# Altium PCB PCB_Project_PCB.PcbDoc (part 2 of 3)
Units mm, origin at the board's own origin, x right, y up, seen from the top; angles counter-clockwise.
Board outline 185 x 95 mm, 2 copper layers (Top Layer, Bottom Layer), stack 1.575 mm thick; 173 components, 93 nets, 424 pads, 126 vias.
Unrouted connection lines stored in the file: 1.
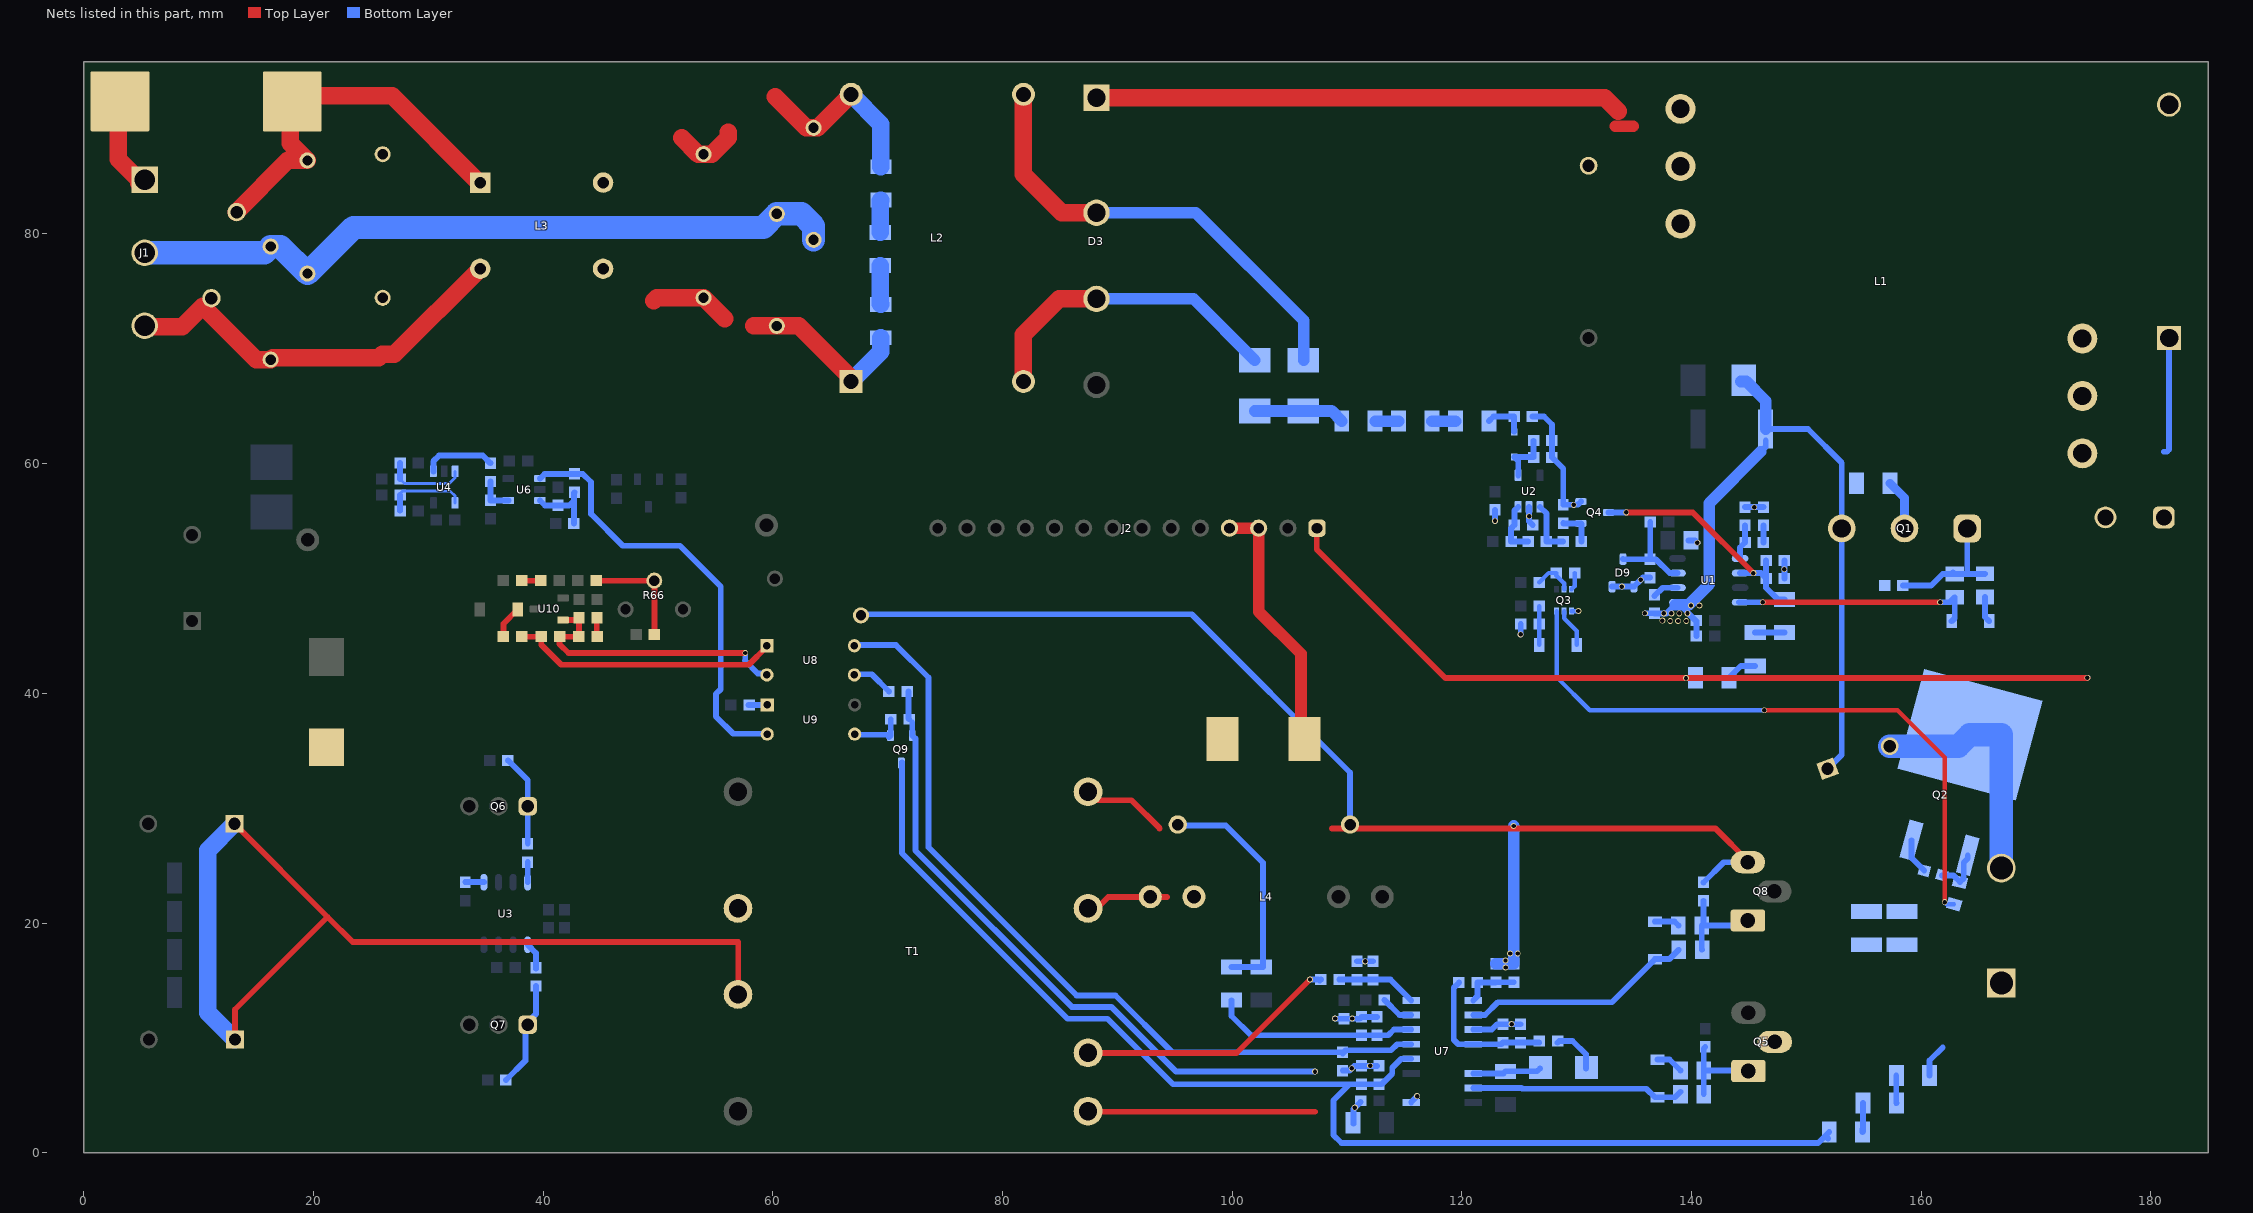
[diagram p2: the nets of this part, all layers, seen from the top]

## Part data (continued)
C48: "CAP, CERM, 0.12 µF, 25 V,+/- 10%, X7R, 0603", Cap_Case=0603, Manufacturer=MuRata, Supplier Part Number 1=GRM188R71E124KA01D-ND, TempCo=X7R, Tolerance_%=10, Value2=25V, ValueDisplayed=0.12µF
C50: "CAP, CERM, 0.33 µF, 16 V,+/- 10%, X7R, 0603", Cap_Case=0603, Manufacturer=MuRata, Supplier Part Number 1=490-3294-1-ND, TempCo=X7R, Tolerance_%=10, Value2=16V, ValueDisplayed=0.33µF
C51: "CAP, CERM, 1000 pF, 100 V,+/- 5%, X7R, 0603", Cap_Case=0603, Manufacturer=AVX, Supplier Part Number 1=478-3698-1-ND, TempCo=X7R, Tolerance_%=5, Value1="0.276 ohm", Value2=100V, ValueDisplayed=1000pF
C52: "CAP, CERM, 47 µF, 25 V,+/- 20%, JB, 1206", Cap_Case=1206, Manufacturer=TDK, Supplier Part Number 1=445-11717-1-ND, TempCo=JB, Tolerance_%=20, Value2=25V, ValueDisplayed=47µF
C54: library part CMP-0007347-5, "CAP, CERM, 4.7 uF, 25 V, +/- 10%, X5R, 0603", Cap_Case=0603, Manufacturer=MuRata, Supplier Part Number 1=490-7203-1-ND, TempCo=X5R, Tolerance_%=10%, Value1=Unknown, Value2=25V, ValueDisplayed=4.7uF
C55: "CAP, CERM, 10 pF, 50 V,+/- 5%, C0G/NP0, 0603", Cap_Case=0603, Manufacturer=MuRata, Supplier Part Number 1=490-1403-1-ND, TempCo=C0G/NP0, Tolerance_%=5, Value2=50V, ValueDisplayed=DNP
C57: library part CMP-0007377-4, "CAP, CERM, 0.01 uF, 16 V, +/- 10%, X7R, 0603", Cap_Case=0603, Manufacturer=MuRata, Supplier Part Number 1=490-1525-1-ND, TempCo=X7R, Tolerance_%=10%, Value1=Unknown, Value2=16V, ValueDisplayed=0.01uF
D1: "Diode, Switching-Bridge, 600 V, 3 A, TH", Manufacturer=Vishay-Semiconductor, Supplier Part Number 1=1N5406-E3/54GICT-ND, Value1=3A, Value2=1.2V
D2: "Diode, Ultrafast, 600 V, 8 A, TH", Manufacturer="ON Semiconductor", Supplier Part Number 1=MUR860GOS-ND, Value1=8A, Value2=0.98V
D3: library part GBJ2510-F, "Diode, Switching-Bridge, 600 V, 25 A, TH", Manufacturer=Vishay, Supplier Part Number 1=GBJ2510-FDI-ND, Value1=25A, Value2=1.05V
D4 D5 D15: "Diode, P-N, 1000 V, 1 A, SMB", Manufacturer="Diodes Inc.", Supplier Part Number 1=RS1MB-FDICT-ND, Value1=1A, Value2=1.3V
D6 D10 D11: library part CMP-0028358-1, "Diode, Schottky, 70 V, 0.015 A, SOD-123", Manufacturer="Diodes Inc.", PartNumber=1N5711W-7-F, Supplier Part Number 1=1N5711WDICT-ND, Value1=0.015A, Value2=1V
D7: "Diode, Schottky, 30V, 0.2A, SOD-323", Alternate PartNumber=BAT54, Manufacturer="ON Semiconductor", Supplier Part Number 1=BAT54HT1OSCT-ND, Value1=0.2A, Value2=0.35V
D8: "Diode, Zener, 5.6 V, 500 mW, SOD-123", Manufacturer="ON Semiconductor", Power_W=0.5, Supplier Part Number 1=MMSZ4690T1GOSCT-ND, Value1=0.5W
D9: "Diode, Switching, 250 V, 0.225 A, SOT-23", Manufacturer=Nexperia, Supplier Part Number 1=568-7986-1-ND, Value1=0.225A, Value2=1.25V
D12: library part MURS360T3G, "Diode, Ultrafast, 600 V, 3 A, SMC", Manufacturer=ST, Supplier Part Number 1=MURS360T3GOSCT-ND, Value1=3A, Value2=1.25V
D13: "Diode, Ultrafast, 600 V, 1 A, SMA", Manufacturer="Diodes Inc.", Supplier Part Number 1=US1J-FDICT-ND, Value1=1A, Value2=1.7V
D14: "Diode, Zener, 30 V, 500 mW, SOD-123", Manufacturer="Diodes Inc.", Power_W=0.5, Supplier Part Number 1=MMSZ5256B-FDICT-ND, Value1=0.5W
F1: library part 0678L9150-02, "Fuse, 10 A, 250 VAC", Irating_A=15, Manufacturer="Bel Fuse", Supplier Part Number 1=507-2062-1-ND
J1: "Header(Shrouded), 6.35mm, 3x1, Tin, TH", Color=Natural, Current_A=12, Manufacturer="TE Connectivity", Supplier Part Number 1=A1468-ND, Voltage_V=600
J2: "Header, 100 mil, 14x1, Tin, R/A, TH", Color=Natural, Manufacturer="TE Connectivity", Supplier Part Number 1=A30868-ND
L2: library part 7448258022, "Common Mode Filters / Chokes 5mH MIN", Manufacturer=Bourns, Supplier Part Number 1=542-8113-RC, Tolerance_%=30, ValueDisplayed="5 mH"
L3: library part 7448051804, "WE-CMBNC Common Mode Power Line Choke Nanocrystalline, Type XL, 4.5mH, 18A, 250V", DC Resistance max.=4.2mOhm, Insulation Test Voltage="1500V (AC)", Operating Temperature="-40 to +125degC", Rated Current=18A, Rated Voltage="250V (AC)"
L5: library part CMP-0062077-1, "Inductor, Ferrite, 300 nH, 32 A, 0.00031 ohm, SMD", Manufacturer="Pulse Engineering", Supplier Part Number 1=553-2161-1-ND, Value1="0.00031 ohm", Value2=32A, ValueDisplayed=300nH
Q1: "MOSFET, N-CH, 600 V, 31 A, TO-247", Alternate Manufacturer=None, Manufacturer="Infineon Technologies", Supplier Part Number 1=IPW60R099CP-ND, Value1="? ohm", Value2="60 nC"
Q2: library part AOB20S60L, "MOSFET, N-CH, 600 V, 20 A, DDPAK", Alternate Manufacturer=None, Manufacturer=AOS, Supplier Part Number 1=785-1247-1-ND, Value1="? ohm", Value2="19.8 nC"
Q3: library part "BC 846PN H6327, Infineon Technologies", "Transistor, NPN/PNP Pair, 65 V, 0.1 A, SOT-363", Manufacturer="Infineon Technologies", Supplier Part Number 1="BC 846PN H6327CT-ND", Value1="0.1 A", Value2=450
Q4 Q9: "MOSFET, N-CH, 60 V, 115 A, SOT-23", Alternate Manufacturer=None, Manufacturer="Fairchild Semiconductor", Supplier Part Number 1=2N7002NCT-ND, Value1="? ohm", Value2="? nC"
Q5 Q8: "MOSFET, N-CH, 650 V, 20.7 A, TO-220AB", Alternate Manufacturer=None, Manufacturer="Infineon Technologies", Supplier Part Number 1=SPP20N65C3XKSA1-ND, Value1="? ohm", Value2="87 nC"
Q6 Q7: library part CMP-0860023-1, "MOSFET, N-CH, 150 V, 100 A,", Alternate Manufacturer=None, Manufacturer="Infineon Technologies", Value1="? ohm", Value2="70 nC"
R1 R31 R41 R46 R50 R59: "RES, 10 k, 5%, 0.1 W, 0603", Manufacturer=Vishay-Dale, Power_W=0.1, Supplier Part Number 1=541-10KGCT-ND, TempCo="200 ppm/C", Tolerance_%=5, Value1=5%, Value2=0.1W, Value_Code=10k0, ValueDisplayed=10k
R2: "RES, 18.2, 1%, 0.125 W, 0805", Manufacturer=Vishay-Dale, Power_W=0.125, Supplier Part Number 1=541-18.2CCT-ND, TempCo="100 ppm/C", Tolerance_%=1, Value1=1%, Value2=0.125W, Value_Code=18R2, ValueDisplayed=18.2
R3: "RES, 0.02, 1%, 2 W, 2512", Manufacturer="Stackpole Electronics Inc", Power_W=2, Supplier Part Number 1=CSRN2512FK20L0CT-ND, TempCo="200 ppm/C", Tolerance_%=1, Value1=1%, Value2=2W, Value_Code=R020, ValueDisplayed=0.02
R4: library part CMP-0022705-3, "RES, 49.9 k, 1%, 0.1 W, AEC-Q200 Grade 0, 0603", Manufacturer=Panasonic, Power_W=100mW, Supplier Part Number 1=P49.9KHCT-ND, TempCo="100 ppm/C", Tolerance_%=1%, Value2=0.1W, Value_Code=49k9, ValueDisplayed=49.9k
R5: "RES, 3.3, 5%, 0.125 W, 0805", Manufacturer=Vishay-Dale, Power_W=0.125, Supplier Part Number 1=541-3.3ACT-ND, TempCo="200 ppm/C", Tolerance_%=5, Value1=5%, Value2=0.125W, Value_Code=3R30, ValueDisplayed=3.3
R6: "RES, 10, 5%, 0.125 W, 0805", Manufacturer=Vishay-Dale, Power_W=0.125, Supplier Part Number 1=541-10ACT-ND, TempCo="200 ppm/C", Tolerance_%=5, Value1=5%, Value2=0.125W, Value_Code=10R0, ValueDisplayed=10
R7 R9 R12: "RES, 3.0 M, 5%, 0.25 W, 1206", Manufacturer=Vishay-Dale, Power_W=0.25, Supplier Part Number 1=541-3.0MECT-ND, TempCo="200 ppm/C", Tolerance_%=5, Value1=5%, Value2=0.25W, Value_Code=3M00, ValueDisplayed=3.0M
R8 R16: "RES, 330 k, 5%, 0.25 W, 1206", Manufacturer=Vishay-Dale, Power_W=0.25, Supplier Part Number 1=541-330KECT-ND, TempCo="200 ppm/C", Tolerance_%=5, Value1=5%, Value2=0.25W, Value_Code=330k
R10: "RES, 10 k, 5%, 0.1 W, 0603", Manufacturer="Yageo America", Power_W=0.1, Supplier Part Number 1=311-10KGRCT-ND, TempCo="100 ppm/C", Tolerance_%=5, Value1=5%, Value2=0.1W, Value_Code=10k0, ValueDisplayed=10k
R11: "RES, 340 k, 1%, 0.25 W, 1206", Manufacturer=Vishay-Dale, Power_W=0.25, Supplier Part Number 1=541-340KFCT-ND, TempCo="100 ppm/C", Tolerance_%=1, Value1=1%, Value2=0.25W, Value_Code=340k
R13: "RES, 1.0 k, 5%, 0.1 W, 0603", Manufacturer=Vishay-Dale, Power_W=0.1, Supplier Part Number 1=541-1.0KGCT-ND, TempCo="200 ppm/C", Tolerance_%=5, Value1=5%, Value2=0.1W, Value_Code=1k00, ValueDisplayed=1.0k
R14: "RES, 220, 5%, 0.1 W, 0603", Manufacturer=Vishay-Dale, Power_W=0.1, Supplier Part Number 1=541-220GCT-ND, TempCo="200 ppm/C", Tolerance_%=5, Value1=5%, Value2=0.1W, Value_Code=220R, ValueDisplayed=220
R15 R18 R29 R40: "RES, 100 k, 5%, 0.1 W, 0603", Manufacturer=Vishay-Dale, Power_W=0.1, Supplier Part Number 1=541-100KGCT-ND, TempCo="200 ppm/C", Tolerance_%=5, Value1=5%, Value2=0.1W, Value_Code=100k
R17: "RES, 2.0 M, 5%, 0.1 W, 0603", Manufacturer=Vishay-Dale, Power_W=0.1, Supplier Part Number 1=541-2.0MGCT-ND, TempCo="200 ppm/C", Tolerance_%=5, Value1=5%, Value2=0.1W, Value_Code=2M00, ValueDisplayed=2.0M
R19: "RES, 12 k, 5%, 0.1 W, 0603", Manufacturer=Vishay-Dale, Power_W=0.1, Supplier Part Number 1=541-12KGCT-ND, TempCo="200 ppm/C", Tolerance_%=5, Value1=5%, Value2=0.1W, Value_Code=12k0, ValueDisplayed=12k
R20: "RES, 22 k, 5%, 0.1 W, 0603", Manufacturer=Vishay-Dale, Power_W=0.1, Supplier Part Number 1=541-22KGCT-ND, TempCo="200 ppm/C", Tolerance_%=5, Value1=5%, Value2=0.1W, Value_Code=22k0, ValueDisplayed=22k
R21: "RES, 13.0 k, 1%, 0.1 W, 0603", Manufacturer=Vishay-Dale, Power_W=0.1, Supplier Part Number 1=541-13.0KHCT-ND, TempCo="100 ppm/C", Tolerance_%=1, Value1=1%, Value2=0.1W, Value_Code=13k0, ValueDisplayed=13.0k
R22: "RES, 33 k, 5%, 0.125 W, 0805", Manufacturer=Vishay-Dale, Power_W=0.125, Supplier Part Number 1=541-33KACT-ND, TempCo="200 ppm/C", Tolerance_%=5, Value1=5%, Value2=0.125W, Value_Code=33k0, ValueDisplayed=33k
R23: "RES, 24 k, 5%, 0.1 W, 0603", Manufacturer="Yageo America", Power_W=0.1, Supplier Part Number 1=311-24KGRCT-ND, TempCo="100 ppm/C", Tolerance_%=5, Value1=5%, Value2=0.1W, Value_Code=24k0, ValueDisplayed=24k
R24 R64: "RES, 127 k, 1%, 0.1 W, 0603", Manufacturer=Vishay-Dale, Power_W=0.1, Supplier Part Number 1=541-127KHCT-ND, TempCo="100 ppm/C", Tolerance_%=1, Value1=1%, Value2=0.1W, Value_Code=127k
R25: "RES, 1.18 M, 1%, 0.1 W, 0603", Manufacturer=Vishay-Dale, Power_W=0.1, Supplier Part Number 1=541-1.18MHCT-ND, TempCo="100 ppm/C", Tolerance_%=1, Value1=1%, Value2=0.1W, Value_Code=1M18, ValueDisplayed=1.18M
R26 R65: "RES, 9.1 k, 5%, 0.1 W, 0603", Manufacturer=Vishay-Dale, Power_W=0.1, Supplier Part Number 1=541-9.1KGCT-ND, TempCo="200 ppm/C", Tolerance_%=5, Value1=5%, Value2=0.1W, Value_Code=9k10, ValueDisplayed=9.1k
R27 R35: library part CMP-0021945-2, "RES, 5.60, 1%, 0.125 W, 0805", Manufacturer="Yageo America", Power_W=125mW, Supplier Part Number 1=311-5.60CRCT-ND, TempCo="200 ppm/C", Tolerance_%=1%, Value2=0.125W, Value_Code=5R60, ValueDisplayed=5.60
R28 R42 R48: "RES, 2.0, 5%, 0.1 W, 0603", Manufacturer=Vishay-Dale, Power_W=0.1, Supplier Part Number 1=541-2.0GCT-ND, TempCo="200 ppm/C", Tolerance_%=5, Value1=5%, Value2=0.1W, Value_Code=2R00, ValueDisplayed=2.0
R30 R37: library part CMP-0021894-2, "RES, 1.00, 1%, 0.125 W, 0805", Manufacturer="Yageo America", Power_W=125mW, Supplier Part Number 1=311-1.00CRCT-ND, TempCo="200 ppm/C", Tolerance_%=1%, Value2=0.125W, Value_Code=1R00, ValueDisplayed=1.00
R32: "RES, 30, 5%, 0.1 W, 0603", Manufacturer=Vishay-Dale, Power_W=0.1, Supplier Part Number 1=541-30GCT-ND, TempCo="200 ppm/C", Tolerance_%=5, Value1=5%, Value2=0.1W, Value_Code=30R0, ValueDisplayed=30
R33: "RES, 33 k, 5%, 0.1 W, 0603", Manufacturer=Vishay-Dale, Power_W=0.1, Supplier Part Number 1=541-33KGCT-ND, TempCo="200 ppm/C", Tolerance_%=5, Value1=5%, Value2=0.1W, Value_Code=33k0, ValueDisplayed=33k
R34: "RES, 51 k, 5%, 0.1 W, 0603", Manufacturer=Vishay-Dale, Power_W=0.1, Supplier Part Number 1=541-51KGCT-ND, TempCo="200 ppm/C", Tolerance_%=5, Value1=5%, Value2=0.1W, Value_Code=51k0, ValueDisplayed=51k
R36: library part CMP-0015849-2, "RES, 0.0005, 1%, 2 W, 2512", Manufacturer=Vishay-Dale, Power_W=2W, TempCo="400 ppm/C", Tolerance_%=1%, Value_Code=L5000, ValueDisplayed=0.0005
R38: "RES, 8.2 k, 5%, 0.1 W, 0603", Manufacturer=Vishay-Dale, Power_W=0.1, Supplier Part Number 1=541-8.2KGCT-ND, TempCo="200 ppm/C", Tolerance_%=5, Value1=5%, Value2=0.1W, Value_Code=8k20, ValueDisplayed=8.2k
R39: "RES, 68, 5%, 0.1 W, 0603", Manufacturer=Vishay-Dale, Power_W=0.1, Supplier Part Number 1=541-68GCT-ND, TempCo="200 ppm/C", Tolerance_%=5, Value1=5%, Value2=0.1W, Value_Code=68R0, ValueDisplayed=68
R43 R44: library part CMP-0022004-4, "RES, 10.0, 1%, 0.25 W, AEC-Q200 Grade 0, 0603", Manufacturer=Vishay-Dale, Power_W=250mW, Supplier Part Number 1=541-10.0SCT-ND, TempCo="100 ppm/C", Tolerance_%=1%, Value2=0.25W, Value_Code=10R0, ValueDisplayed=10.0
R45: "RES, 1.0 k, 5%, 0.1 W, 0603", Manufacturer="Yageo America", Power_W=0.1, Supplier Part Number 1=311-1.0KGRCT-ND, TempCo="100 ppm/C", Tolerance_%=5, Value1=5%, Value2=0.1W, Value_Code=1k00, ValueDisplayed=1.0k
R47: "RES, 24.3 k, 1%, 0.1 W, 0603", Manufacturer=Vishay-Dale, Power_W=0.1, Supplier Part Number 1=541-24.3KHCT-ND, TempCo="100 ppm/C", Tolerance_%=1, Value1=1%, Value2=0.1W, Value_Code=24k3, ValueDisplayed=24.3k
R49: "RES, 110 k, 5%, 0.1 W, 0603", Manufacturer=Vishay-Dale, Power_W=0.1, Supplier Part Number 1=541-110KGCT-ND, TempCo="200 ppm/C", Tolerance_%=5, Value1=5%, Value2=0.1W, Value_Code=110k
R51 R53: "RES, 5.1 M, 5%, 0.25 W, 1206", Manufacturer=Vishay-Dale, Power_W=0.25, Supplier Part Number 1=541-5.1MECT-ND, TempCo="200 ppm/C", Tolerance_%=5, Value1=5%, Value2=0.25W, Value_Code=5M10, ValueDisplayed=5.1M
R52: "RES, 75 k, 5%, 0.1 W, 0603", Manufacturer=Vishay-Dale, Power_W=0.1, Supplier Part Number 1=541-75KGCT-ND, TempCo="200 ppm/C", Tolerance_%=5, Value1=5%, Value2=0.1W, Value_Code=75k0, ValueDisplayed=75k
R54: "RES, 470 k, 5%, 0.1 W, 0603", Manufacturer=Vishay-Dale, Power_W=0.1, Supplier Part Number 1=541-470KGCT-ND, TempCo="200 ppm/C", Tolerance_%=5, Value1=5%, Value2=0.1W, Value_Code=470k
R55: "RES, 6.04 k, 1%, 0.1 W, 0603", Manufacturer=Vishay-Dale, Power_W=0.1, Supplier Part Number 1=541-6.04KHCT-ND, TempCo="100 ppm/C", Tolerance_%=1, Value1=1%, Value2=0.1W, Value_Code=6k04, ValueDisplayed=6.04k
R56: "RES, 130 k, 5%, 0.1 W, 0603", Manufacturer=Vishay-Dale, Power_W=0.1, Supplier Part Number 1=541-130KGCT-ND, TempCo="200 ppm/C", Tolerance_%=5, Value1=5%, Value2=0.1W, Value_Code=130k
R57 R63: "RES, 10 k, 5%, 0.1 W, 0603", Manufacturer="Samsung Electro-Mechanics", Power_W=0.1, Supplier Part Number 1=1276-5086-1-ND, TempCo="100 ppm/C", Tolerance_%=5, Value1=5%, Value2=0.1W, Value_Code=10k0, ValueDisplayed=10k
R58: "RES, 0, 1%, 0.1 W, AEC-Q200 Grade 0, 0603", Manufacturer="Stackpole Electronics Inc", Power_W=0.1, Supplier Part Number 1=RMCF0603ZT0R00CT-ND, TempCo=ppm/C, Tolerance_%=1, Value1=1%, Value2=0.1W, Value_Code=0
R60: "RES, 5.6 M, 5%, 0.25 W, 1206", Manufacturer=Vishay-Dale, Power_W=0.25, Supplier Part Number 1=541-5.6MECT-ND, TempCo="200 ppm/C", Tolerance_%=5, Value1=5%, Value2=0.25W, Value_Code=5M60, ValueDisplayed=5.6M
R61: "RES, 330 k, 5%, 0.1 W, 0603", Manufacturer=Vishay-Dale, Power_W=0.1, Supplier Part Number 1=541-330KGCT-ND, TempCo="200 ppm/C", Tolerance_%=5, Value1=5%, Value2=0.1W, Value_Code=330k
R62: "RES, 0, 5%, 0.1 W, 0603", Manufacturer=Vishay-Dale, Power_W=0.1, Supplier Part Number 1=541-0.0GCT-ND, TempCo="200 ppm/C", Tolerance_%=5, Value1=5%, Value2=0.1W, Value_Code=0000, ValueDisplayed=0
R66: library part CMP-0001795-2, "Trimmer Potentiometer, Lead Sealed Type Multiturn PV37 Series, TH", Manufacturer=Bourns, Supplier Part Number 1=490-2983-ND
R67 R68 R69: library part CMP-0018205-2, "RES, 330 k, 1%, 0.25 W, 1206", Manufacturer="Yageo America", Power_W=250mW, Supplier Part Number 1=311-330KFRCT-ND, TempCo="100 ppm/C", Tolerance_%=1%, Value2=0.25W, Value_Code=330k
RF1: "RES, 47, 10%, 2 W, Axial resistor", Manufacturer="TT Electronics/IRC", Power_W=2, Supplier Part Number 1=985-1022-1-ND, TempCo="100 ppm/C", Tolerance_%=10, Value1=10%, Value2=2W, Value_Code=47R0, ValueDisplayed=47
RV1: "Varistor 275V RMS 10MM Radial, TH", Manufacturer=TDK, Supplier Part Number 1=495-1433-ND
T1: library part 760895431, "WE-LLCR Resonant Converter, size PQ3232, 155uH, 16:4:4:1 , 500W", Inductance=600uH, Input Voltage="360-400 V DC", Output Power=500W
U1: library part CMP-0074100-1, "8-PIN CONTINUOUS CONDUCTION MODE (CCM) PFC CONTROLLER, D0008A (SOIC-8)", Alternate Manufacturer="Texas Instruments", Alternate PartNumber=UCC28180D
U2: library part CMP-0073526-1, "36V, Low-Power, RRO, General-Purpose Operational Amplifier, DBV0005A (SOT-23-5)", Alternate Manufacturer="Texas Instruments", Alternate PartNumber=TLV171IDBVT
U3: library part CMP-0079610-1, "High Performance Synchronous Rectifier Driver for LLC Resonant Converter, D0008A (SOIC-8)", Alternate Manufacturer="Texas Instruments"
U4: library part CMP-0013052-2, "Low- and High-Side Measurement, Multichannel, Voltage Output, Current-Sense Amplifier, DBV0005A (SOT-5)", Alternate Manufacturer="Texas Instruments"
U5: library part CMP-0074893-1, "100-mA, 30-V, Fixed-Output, Linear-Voltage Regulator, DBZ0003A (SOT-23-3)", Alternate Manufacturer="Texas Instruments", Alternate PartNumber=TLV76033DBZT
U6: library part CMP-0081550-1, "Low-Power, Rail-to-Rail In and Out, 1-MHz Operational Amplifier, DBV0005A (SOT-23-5)", Alternate Manufacturer="Texas Instruments", Alternate PartNumber=TLV9001IDBVT
U7: library part CMP-0077204-4, "LLC Resonant Controller Enabling Low Standby Power, DDB0014A (SOIC-14)", Alternate Manufacturer="Texas Instruments", Alternate PartNumber=UCC25630-3DDBT, Operating Temperature Range="-40 to 125 C", PartNumber=UCC25640-3DDBR, Rating=Catalog
U8 U9: "Optocoupler, 5.3 kV, 50-600% CTR, TH", Manufacturer=Vishay-Semiconductor, Supplier Part Number 1=VO618A-ND, Voltage_Isolation_Vrms=5300V
U10: library part CMP-0066200-1, "2.5V Low Iq Adjustable Precision Shunt Regulator, DBZ0003A (SOT-23-3)", Alternate Manufacturer="Texas Instruments", Alternate PartNumber=ATL431BQDBZT
ZZ1: library part CMP-0003616-3
ZZ2: library part CMP-0077236-1
ZZ3: library part CMP-0077237-1
ZZ4: library part CMP-0077238-1

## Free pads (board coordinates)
  round 2 hole 1.2: 2(59.461,54.635) 3(19.507,53.365)

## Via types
v1: diameter 0.508, hole 0.381, Top Layer to Bottom Layer, 124 vias
v2: diameter 2.54, hole 2.032, Top Layer to Bottom Layer, 2 vias

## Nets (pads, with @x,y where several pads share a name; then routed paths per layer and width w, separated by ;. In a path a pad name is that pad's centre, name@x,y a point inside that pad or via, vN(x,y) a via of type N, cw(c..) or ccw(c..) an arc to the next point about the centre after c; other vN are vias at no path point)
12V: C49.1 C54.2 R48.1 R54.2 U7.12 | length 12.8
  Bottom Layer w0.508: R54.2@119.753,14.808 119.304,14.359 119.304,9.83 119.685,9.449 U7.12@120.992,9.449 123.435,9.449 C54.2@123.575,9.589 C49.1@125.099,9.589 126.725,9.589 R48.1@126.738,9.576
390V: C1.1 C6.1 C7.1 D1.1 D2.1 J2.1 Q5.2 R8.2 R51.2 | length 87.6
  Top Layer w0.508: J2.1@107.366,54.381 107.366,52.527 118.567,41.326 v1(139.522,41.326) 174.447,41.326 v1(174.473,41.351)
  Bottom Layer w0.508: v1(139.522,41.326) 139.548,41.351 R8.2@140.358,41.351 ; R51.2@160.733,6.731 160.733,8.029 161.874,9.169 ; 181.127,61.036 181.381,61.036 181.585,61.239 D1.1@181.585,70.942
ACSNS: C14.1 D7.1 R17.2 U2.4 | length 4.9
  Bottom Layer w0.508: U2.4@124.907,58.982 124.907,60.226 D7.1@124.562,60.571 126.233,60.571 C14.1@126.251,60.554 R17.2@126.251,62.001
BLK: C57.1 Q9.3 R60.1 R64.2 U7.4 | length 111
  Bottom Layer w0.508: Q9.3@71.247,34.004 71.247,26.086 85.674,11.659 89.154,11.659 94.856,5.956 110.223,5.956 ; U7.4@115.592,8.179 114.732,8.179 113.944,7.391 113.944,6.883 113.017,5.956 C57.1@112.776,5.956 R64.2@111.256,5.956 110.223,5.956 ; R60.1@151.892,1.245 R60.1@151.663,1.473 ; R60.1@151.994,1.803 R60.1@151.663,1.473 ; 110.223,5.956 108.814,4.547 108.814,1.549 109.525,0.838 151.028,0.838 R60.1@151.663,1.473
BW: C56.1 R33.1 R38.2 U7.8 | length 7
  Bottom Layer w0.508: R33.1@109.334,15.088 109.347,15.075 C56.1@110.875,15.075 R38.2@112.272,15.075 113.776,15.075 U7.8@115.592,13.259
DRV: Q3.3 R2.2 | length 55.9
  Top Layer w0.381: v1(146.329,38.532) 157.937,38.532 162.052,34.417 v1(162.052,21.819)
  Bottom Layer w0.381: Q3.3@128.255,47.163 128.255,41.417 131.14,38.532 v1(146.329,38.532) ; v1(162.052,21.819) 162.231,21.64 R2.2@162.86,21.64
EARTH: C2.2 C3.1 C11.1 C12.1 J1.2 | length 63.5
  Bottom Layer w1.016: J1.2@5.08,78.359 J1.2@5.309,78.359
  Bottom Layer w2.032: J1.2@5.309,78.359 15.739,78.359 C3.1@16.282,78.902 17.136,78.902 C12.1@19.482,76.556 23.487,80.561 59.165,80.561 C2.2@60.351,81.746 62.5,81.746 63.551,80.696 C11.1@63.551,79.493
FB: C51.1 U7.5 U8.4 | length 72.2
  Bottom Layer w0.508: U8.4@67.107,44.196 70.739,44.196 73.558,41.377 73.558,26.594 86.462,13.691 89.84,13.691 94.78,8.75 C51.1@109.626,8.75 ; C51.1@109.626,8.649 109.893,8.915 113.843,8.915 114.376,9.449 U7.5@115.592,9.449
G1: R42.1 U3.1 | length 2.4
  Bottom Layer w0.508: U3.1@38.659,18.103 39.37,17.392 R42.1@39.37,16.015
G2: R28.2 U3.8 | length 1.8
  Bottom Layer w0.508: U3.8@38.659,23.553 R28.2@38.659,25.311
HO: D10.1 R27.1 U7.15 | length 18.6
  Bottom Layer w0.508: U7.15@120.992,5.639 125.197,5.639 125.261,5.574 136.069,5.574 136.818,4.826 138.557,4.826 R27.1@139.04,5.309
I_OUT: R45.1 U4.1 | length 6.3
  Bottom Layer w0.508: U4.1@30.444,59.325 30.444,60.2 30.95,60.706 34.747,60.706 R45.1@35.408,60.045
ISNS: C26.2 C38.1 R39.2 U7.6 | length 17.9
  Bottom Layer w0.508: C26.2@99.949,13.282 99.949,11.913 101.638,10.224 R39.2@111.256,10.224 C38.1@112.628,10.224 113.602,10.224 114.097,10.719 U7.6@115.592,10.719
LATCH: R49.1 U6.1 U9.2 | length 38.2
  Bottom Layer w0.508: U6.1@39.729,58.697 40.138,59.106 R49.1@42.748,59.106 43.46,59.106 44.171,58.395 44.171,55.626 46.939,52.857 51.918,52.857 55.474,49.301 55.474,40.361 55.067,39.954 55.067,37.973 56.566,36.474 U9.2@59.512,36.474
LL/SS: C50.1 R54.1 R61.2 U7.9 | length 4.9
  Bottom Layer w0.508: U7.9@120.992,13.259 121.353,13.619 R54.1@121.353,14.808 122.927,14.808 R61.2@122.966,14.846 C50.1@124.515,14.846
LO: D11.1 R35.1 U7.10 | length 20.3
  Bottom Layer w0.508: U7.10@120.992,11.989 122.022,11.989 123.139,13.106 133.071,13.106 D11.1@136.818,16.854 ; D11.1@136.804,16.854 D11.1@136.818,16.854 ; R35.1@138.887,17.678 138.063,16.854 D11.1@136.818,16.854
NetA: D4.1 D5.1 R7.2 | length 7.9
  Bottom Layer w1.016: D5.1@101.981,64.592 D4.1@106.197,64.592 108.659,64.592 R7.2@109.548,63.703
NetC1_2: C1.2 Q2.4 RF1.2 | length 21.8
  Bottom Layer w2.032: RF1.2@157.259,35.396 163.235,35.396 Q2.4@164.243,36.404 166.98,36.404 C1.2@166.98,24.787
NetC2_1: C2.1 C10.1 L2.6 L3.4 R67.2 | length 22
  Top Layer w1.524: 52.07,88.367 53.491,86.946 C10.1@53.975,86.946 54.688,86.946 56.134,88.392 56.134,88.875 ; 60.228,91.944 62.925,89.246 C2.1@63.551,89.246 63.916,89.246 L2.6@66.827,92.158
  Bottom Layer w1.524: L2.6@66.827,92.158 69.418,89.567 R67.2@69.418,85.854
NetC3_2: C3.2 C4.1 F1.1 L3.1 RV1.2 | length 33.7
  Top Layer w1.524: RV1.2@13.267,81.906 17.762,86.402 C3.2@19.482,86.402 17.997,87.886 17.997,91.542 18.478,92.022 25.984,92.022 26.85,92.022 L3.1@34.464,84.408
NetC4_2: C4.2 C12.2 J1.3 L3.2 RV1.1 | length 35.4
  Top Layer w1.524: J1.3@5.08,71.933 8.594,71.933 10.367,73.707 15.018,69.056 C12.2@16.282,69.056 16.467,69.24 25.703,69.24 25.984,69.522 27.053,69.522 L3.2@34.515,76.984
NetC5_1: C5.1 D1.2 D3.1 L1.1 | length 47.5
  Top Layer w1: 133.368,89.383 134.925,89.383
  Top Layer w1.524: D3.1@88.189,91.853 132.427,91.853 133.604,90.676
NetC10_2: C10.2 C11.2 L2.1 L3.3 R69.1 | length 22.6
  Top Layer w1.524: 49.632,74.193 49.884,74.446 C10.2@53.975,74.446 53.977,74.446 55.804,72.619 ; 58.353,71.993 C11.2@60.351,71.993 62.272,71.993 66.827,67.437 L2.1@66.827,67.158
  Bottom Layer w1.524: L2.1@66.827,67.158 69.407,69.738 R69.1@69.407,70.965
NetC13_1: C13.1 D2.3 L1.2 Q1.2 | length 4.5
  Bottom Layer w0.762: C13.1@157.279,58.293 158.547,57.025 Q1.2@158.547,54.356
NetC15_1: C15.1 D8.1 R13.1 | length 3.4
  Bottom Layer w0.381: D8.1@126.734,44.221 C15.1@126.733,46.05 R13.1@126.733,47.6
NetC16_1: C16.1 D9.3 R14.1 U1.3 | length 8.5
  Bottom Layer w0.508: D9.3@134.036,51.695 134.055,51.676 C16.1@136.398,51.676 ; R14.1@136.411,54.915 136.411,51.689 C16.1@136.398,51.676 ; U1.3@138.778,50.469 138.1,50.469 136.893,51.676 C16.1@136.398,51.676
NetC18_1: C18.1 U1.2 | length 2.3
  Bottom Layer w0.508: C18.1@136.779,48.49 137.488,49.199 U1.2@138.778,49.199
NetC19_1: C19.1 Q4.3 R16.1 R21.2 U1.6 | length 21.7
  Top Layer w0.508: v1(134.315,55.753) 140.106,55.753 v1(145.39,50.469)
  Bottom Layer w0.508: Q4.3@132.772,55.753 v1(134.315,55.753) ; U1.6@144.228,50.469 v1(145.39,50.469) 146.038,50.469 R21.2@146.495,50.013 ; C19.1@146.495,51.562 R21.2@146.495,50.013 ; 146.507,49.2 146.495,49.212 ; R16.1@148.107,48.186 147.509,48.186 146.495,49.2 146.495,49.212 ; 146.495,49.212 R21.2@146.495,50.013
NetC20_1: C20.1 R20.2 U1.5 | length 3.1
  Bottom Layer w0.508: U1.5@144.228,51.739 144.228,52.699 R20.2@144.666,53.137 144.653,53.15 C20.1@144.653,54.622
NetC21_1: C21.1 R20.1 | length 1.5
  Bottom Layer w0.508: R20.1@146.266,53.137 146.279,53.15 C21.1@146.279,54.622
NetC25_1: C25.1 C26.1 C31.1 D12.1 T1.3 | length 27.9
  Top Layer w0.508: T1.3@87.478,30.694 91.237,30.694 93.687,28.245
  Bottom Layer w0.508: C31.1@95.268,28.245 95.522,28.499 99.441,28.499 102.692,25.248 102.692,16.182 C25.1@102.54,16.182 C26.1@99.949,16.182
NetC27_1: C27.1 C28.1 C32.1 C33.1 C34.1 C35.1 L5.1 T1.9 T1.10 | length 88.2
  Top Layer w0.508: C27.1@13.123,28.642 21.23,20.534 ; C28.1@13.173,9.855 13.173,12.478 21.23,20.534 ; T1.9@56.998,13.044 56.998,18.339 23.426,18.339 21.23,20.534
  Bottom Layer w1.524: C27.1@13.123,28.642 10.823,26.342 C34.1@10.823,23.901 C32.1@10.823,17.247 C35.1@10.823,13.945 10.823,12.206 C28.1@13.173,9.855
NetC44_1: C44.1 R43.1 U4.3 | length 7.1
  Bottom Layer w0.254: R43.1@27.546,58.661 27.927,58.28 31.826,58.28 32.344,58.798 U4.3@32.344,59.325
  Bottom Layer w0.508: R43.1@27.546,58.661 C44.1@27.546,60.058
NetC45_1: C45.1 R44.1 U4.4 | length 7.1
  Bottom Layer w0.254: R44.1@27.546,57.391 27.775,57.62 31.902,57.62 32.344,57.178 U4.4@32.344,56.575
  Bottom Layer w0.508: C45.1@27.546,55.893 R44.1@27.546,57.264
NetC46_1: C46.1 R45.2 U6.4 | length 3.2
  Bottom Layer w0.508: R45.2@35.408,58.445 C46.1@35.408,56.794 36.976,56.794 U6.4@36.979,56.797
NetC47_1: C47.1 D13.1 U7.14 | length 6
  Bottom Layer w0.508: U7.14@120.992,6.909 123.624,6.909 C47.1@123.804,7.089 126.552,7.089 D13.1@126.803,7.341
NetC48_1: C48.1 R59.2 | length 1.7
  Top Layer w0.508: R59.2@44.679,46.571 44.679,44.971 C48.1@44.717,44.933
NetC48_2: C48.2 C55.2 R55.1 U8.2 U10.1 | length 24.9
  Top Layer w0.508: U10.1@41.738,46.396 42.954,46.396 C55.2@43.117,46.558 ; C55.2@43.129,46.571 C55.2@43.117,46.558 ; v1(57.607,43.51) 42.215,43.51 41.44,44.285 R55.1@41.44,44.933 C48.2@43.117,44.933 C55.2@43.117,46.558
  Bottom Layer w0.508: v1(57.607,43.51) 57.607,42.875 57.582,42.85 58.699,41.732 U8.2@59.461,41.732
NetD3_2: D3.2 D4.2 L2.7 | length 40.1
  Top Layer w1.524: L2.7@81.827,92.158 81.827,85.183 85.157,81.853 D3.2@88.189,81.853
  Bottom Layer w1.016: D3.2@88.189,81.853 96.836,81.853 106.223,72.466 D4.2@106.223,69.012
NetD3_3: D3.3 D5.2 L2.12 | length 27.7
  Top Layer w1.524: L2.12@81.827,67.158 81.827,71.236 84.945,74.353 D3.3@88.189,74.353
  Bottom Layer w1.016: D3.3@88.189,74.353 96.64,74.353 D5.2@101.981,69.012
NetD6_1: D6.1 R6.1 U1.8 | length 21.3
  Top Layer w0.508: v1(146.202,47.93) v1(161.646,47.929)
  Bottom Layer w0.508: U1.8@144.228,47.929 144.127,47.929 v1(146.202,47.93) ; v1(161.646,47.929) 162.483,47.929 R6.1@162.916,48.362 162.916,46.545 D6.1@162.65,46.279
NetD6_2: D6.2 R5.1 | length 2.3
  Bottom Layer w0.508: R5.1@165.557,48.387 165.557,46.646 D6.2@165.925,46.279
NetD7_2: D7.2 R12.1 R18.2 | length 3.7
  Bottom Layer w0.508: R12.1@122.354,63.703 122.76,64.11 R18.2@124.549,64.11 124.549,62.784 D7.2@124.562,62.771
NetD8_2: D8.2 Q3.2 | length 3.4
  Bottom Layer w0.381: Q3.2@128.905,47.163 128.905,46.532 130.009,45.429 D8.2@130.009,44.221
NetD10_2: D10.2 R30.1 | length 2.4
  Bottom Layer w0.508: D10.2@137.033,8.114 138.088,8.114 R30.1@139.04,7.163
NetD11_2: D11.2 R37.1 | length 2.2
  Bottom Layer w0.508: D11.2@136.804,20.129 138.52,20.129 R37.1@138.862,19.787
NetD13_2: D13.2 R48.2 | length 4.2
  Bottom Layer w0.508: R48.2@128.338,9.576 128.49,9.728 129.642,9.728 130.803,8.566 D13.2@130.803,7.341
NetD14_2: D14.2 R50.2 | length 2.9
  Top Layer w0.508: R50.2@36.551,44.933 36.551,46.064 D14.2@37.782,47.295
NetF1_2: F1.2 J1.1 | length 7.9
  Top Layer w1.524: F1.2@2.997,91.542 2.997,86.512 4.775,84.734 J1.1@4.775,84.404
NetL4_2: L4.2 T1.1 | length 7.6
  Top Layer w0.508: T1.1@87.478,20.534 89.209,22.266 94.335,22.266
NetQ1_1: Q1.1 R1.2 R5.2 R6.2 | length 10.7
  Bottom Layer w0.508: R1.2@158.407,49.378 160.858,49.378 161.874,50.394 R6.2@162.916,50.394 ; R6.2@162.763,50.546 R6.2@162.916,50.394 ; Q1.1@164.008,53.264 164.008,50.47 163.932,50.394 ; R5.2@165.557,50.419 165.532,50.394 163.932,50.394 ; R6.2@162.916,50.394 163.932,50.394
NetQ2_1: Q2.1 R2.1 R4.1 | length 4.4
  Bottom Layer w0.508: R4.1@161.809,24.152 162.798,24.152 R2.1@163.378,23.572 163.703,23.897 163.703,25.273 164.056,25.626 Q2.1@164.056,25.894
NetQ3_5: Q3.5 R10.1 R15.2 | length 3.5
  Bottom Layer w0.381: R10.1@126.746,49.662 127.559,50.475 R15.2@128.22,50.475 128.22,50.266 128.905,49.58 Q3.5@128.905,49.063
NetQ3_6: Q3.6 R15.1 | length 1.5
  Bottom Layer w0.381: Q3.6@129.555,49.063 129.82,49.327 R15.1@129.82,50.475
NetQ4_1: Q4.1 R19.1 R23.2 | length 3.2
  Bottom Layer w0.508: R23.2@128.829,54.826 128.852,54.803 Q4.1@130.372,54.803 130.416,54.759 R19.1@130.416,53.213
NetQ5_1: Q5.1 R27.2 R30.2 R31.2 | length 8.1
  Bottom Layer w0.508: R27.2@141.072,5.105 R30.2@141.072,7.163 ; R31.2@141.199,9.208 141.072,9.081 R30.2@141.072,7.163 ; Q5.1@144.958,7.112 144.907,7.163 R30.2@141.072,7.163
NetQ6_1: Q6.1 R28.1 R29.1 | length 8
  Bottom Layer w0.508: R29.1@36.944,34.163 38.659,32.448 Q6.1@38.659,30.175 R28.1@38.659,26.911
NetQ7_1: Q7.1 R40.1 R42.2 | length 9.3
  Bottom Layer w0.508: R40.1@36.766,6.325 38.456,8.014 38.456,11.151 39.37,12.065 R42.2@39.37,14.516
NetQ8_1: Q8.1 R35.2 R37.2 R41.2 | length 8.5
  Bottom Layer w0.508: R35.2@140.919,17.678 140.894,17.704 R37.2@140.894,19.787 ; R41.2@141.046,21.933 141.046,19.939 R37.2@140.894,19.787 ; Q8.1@144.907,20.218 144.475,19.787 R37.2@140.894,19.787
NetQ9_1: Q9.1 R63.1 U9.3 | length 4.5
  Bottom Layer w0.508: U9.3@67.158,36.398 Q9.1@70.015,36.398 ; Q9.1@70.119,36.176 70.269,36.326 R63.1@70.269,37.744
NetR7_1: R7.1 R9.2 | length 2.1
  Bottom Layer w1.016: R7.1@112.448,63.703 R9.2@114.501,63.703
NetR8_1: R8.1 R11.2 | length 2.7
  Bottom Layer w0.508: R8.1@143.258,41.351 144.302,42.395 145.538,42.395 R11.2@145.542,42.39
NetR9_1: R9.1 R12.2 | length 2.1
  Bottom Layer w1.016: R9.1@117.401,63.703 R12.2@119.454,63.703
NetR11_1: R11.1 R16.2 | length 2.6
  Bottom Layer w0.508: R11.1@145.542,45.29 148.103,45.29 R16.2@148.107,45.286
NetR24_1: R24.1 R25.1 R26.2 U2.3 | length 4.7
  Bottom Layer w0.508: U2.3@124.907,56.232 124.574,55.9 R26.2@124.574,54.661 124.295,54.381 R24.1@124.295,53.213 125.763,53.213 R25.1@125.768,53.208
NetR32_2: R32.2 U3.5 | length 1.6
  Bottom Layer w0.508: R32.2@33.223,23.558 34.843,23.558 U3.5@34.849,23.553
NetR33_2: R33.2 T1.5 | length 23.3
  Top Layer w0.508: T1.5@87.478,7.964 88.2,8.687 100.381,8.687 v1(106.782,15.088)
  Bottom Layer w0.508: v1(106.782,15.088) 107.531,15.088 107.633,14.986 R33.2@107.734,15.088
NetR34_2: R34.2 R65.1 R66.2 | length 9.7
  Top Layer w0.508: R65.1@44.64,49.809 R66.2@49.682,49.809 49.695,49.797 R34.2@49.695,45.136
NetR46_2: R46.2 R47.2 R49.2 U6.3 | length 6.1
  Bottom Layer w0.508: U6.3@39.729,56.797 40.163,56.363 R47.2@41.3,56.363 42.253,56.363 42.685,56.794 ; R46.2@42.685,54.788 42.685,56.794 ; R49.2@42.748,57.506 42.685,57.442 42.685,56.794
NetR50_1: R50.1 R55.2 U8.1 | length 23.6
  Top Layer w0.508: R50.1@38.151,44.933 R55.2@39.84,44.933 39.84,44.234 41.58,42.494 57.912,42.494 59.461,44.044 U8.1@59.461,44.272
NetR51_1: R51.1 R53.2 | length 2.4
  Bottom Layer w0.508: R51.1@157.833,6.731 157.833,4.322 R53.2@157.838,4.318
NetR52_1: R52.1 R56.2 | length 1.7
  Top Layer w0.508: R52.1@38.138,49.809 R56.2@39.789,49.809
NetR53_1: R53.1 R60.2 | length 2.8
  Bottom Layer w0.508: R60.2@154.894,2.063 R60.2@154.894,1.803 154.938,1.848 R53.1@154.938,4.318
NetR57_1: R57.1 U9.1 | length 1.6
  Bottom Layer w0.508: R57.1@57.874,38.989 R57.1@57.95,38.989 59.487,38.989 U9.1@59.512,39.014
NetR58_2: R58.2 U7.7 | length 2.9
  Bottom Layer w0.508: R58.2@113.25,13.31 114.571,11.989 U7.7@115.592,11.989
NetR62_2: R62.2 U8.3 | length 3.6
  Bottom Layer w0.508: U8.3@67.107,41.656 68.618,41.656 R62.2@70.117,40.157
NetR67_1: R67.1 R68.2 | length 2.8
  Bottom Layer w1.524: R68.2@69.367,80.139 69.367,82.903 R67.1@69.418,82.954
NetR68_1: R68.1 R69.2 | length 3.4
  Bottom Layer w1.524: R68.1@69.367,77.239 69.367,73.905 R69.2@69.407,73.865
PFC_OFF: R19.2 R25.2 U2.1 | length 4.7
  Bottom Layer w0.508: U2.1@126.807,56.232 127.368,55.671 R25.2@127.368,53.208 128.811,53.208 R19.2@128.816,53.213
PGND: C6.2 C7.2 C9.2 C13.2 C14.2 C15.2 C16.2 C17.2 C18.2 C19.2 C20.2 C21.2 C22.2 C31.2 C38.2 C39.2 C41.1 C49.2 C50.2 C51.2 C52.2 C53.2 C54.1 C56.2 C57.2 D9.1 D9.2 D12.2 D15.2 J2.3 J2.4 Q1.3 Q2.3 Q3.1 Q4.2 Q8.3 Q9.2 R1.1 R3.2 R4.2 R17.1 R18.1 R21.1 R22.1 R23.1 R26.1 R38.1 R39.1 R41.1 R61.1 R62.1 R63.2 R64.1 RF1.1 T1.6 U1.1 U2.2 U7.1 U7.11 | length 313.4
  Top Layer w0.508: T1.6@87.478,3.57 107.228,3.57 ; 108.687,28.245 142.062,28.245 Q8.3@144.958,25.349
  Top Layer w1.016: J2.4@99.771,54.381 J2.3@102.311,54.381 102.311,47.117 105.994,43.434 D12.2@105.994,36.894
  Bottom Layer w0.381: Q3.1@129.555,47.163 130.144,47.163 v1(130.15,47.168)
  Bottom Layer w0.508: C41.1@67.682,46.888 96.495,46.888 110.268,33.115 C31.2@110.268,28.575 ; R62.1@71.806,40.157 71.806,37.808 R63.2@71.869,37.744 ; R63.2@72.146,37.467 Q9.2@72.146,36.328 72.415,36.059 72.415,26.314 86.03,12.7 89.484,12.7 95.123,7.061 v1(107.213,7.061) ; v1(108.966,11.684) 108.979,11.671 C39.2@109.758,11.671 111.104,11.671 R39.1@111.256,11.824 C38.2@112.628,11.824 ; C51.2@109.626,7.15 110.223,7.15 v1(110.414,7.341) 110.63,7.556 R64.1@111.256,7.556 C57.2@112.628,7.556 ; C52.2@110.564,2.515 110.564,3.795 v1(110.693,3.924) C53.2@111.189,4.42 ; C56.2@110.875,16.675 R38.1@112.272,16.675 ; U7.1@115.592,4.369 115.592,4.416 v1(116.103,4.928) ; U7.11@120.992,10.719 122.606,10.719 123.076,11.189 C54.1@123.575,11.189 C49.2@125.099,11.189 ; v1(122.885,55.016) C22.2@122.885,55.969 ; R61.1@122.966,16.446 123.749,16.446 ; v1(125.12,45.136) 125.133,45.149 C15.2@125.133,46.05 ; U2.2@125.857,56.232 v1(125.857,55.423) 125.857,54.978 R26.1@126.174,54.661 ; R18.1@126.149,64.11 127.152,64.11 127.851,63.411 R17.1@127.851,62.001 C14.2@127.851,60.554 128.829,59.576 R23.1@128.829,56.426 130.095,56.426 Q4.2@130.372,56.703 ; D9.2@133.086,49.295 v1(133.934,49.295) D9.1@134.986,49.295 v1(135.576,49.886) 135.767,50.076 C16.2@136.398,50.076 ; v1(135.937,46.977) C18.2@136.779,46.977 136.792,46.965 v1(137.592,46.965) 137.813,46.965 138.124,47.276 138.157,47.308 U1.1@138.576,47.727 ; U1.1@138.981,47.727 140.424,46.284 C9.2@140.424,44.983 ; R22.1@139.738,53.315 R22.1@139.954,53.315 140.31,53.315 v1(140.513,53.111) ; R41.1@141.046,23.533 142.812,25.298 Q8.3@144.907,25.298 ; C20.2@144.653,56.222 C21.2@146.279,56.222 ; 146.012,61.023 146.464,61.475 R3.2@146.464,62.027 ; R3.2@146.46,63.017 150.139,63.017 153.086,60.071 Q1.3@153.086,54.356 153.086,34.658 RF1.1@151.858,33.43 ; R21.1@148.095,50.013 C19.2@148.095,51.562 ; Q2.3@159.149,27.209 159.149,25.68 R4.2@160.263,24.566
  Bottom Layer w1.016: R61.1@122.966,16.446 123.811,16.446 C50.2@124.515,16.446 ; v1@124.515,28.448 C50.2@124.515,16.446 ; C50.2@124.536,16.446 C50.2@124.515,16.446 ; U1.1@138.576,47.727 138.938,47.727 138.981,47.727 139.776,47.727 141.554,49.505 141.554,56.566 146.012,61.023 ; D15.2@144.298,67.159 144.753,67.159 146.46,65.452 R3.2@146.46,63.017
  other v1: 112.014,7.569 124.333,11.201 110.465,11.684 123.811,16.129 111.582,16.662 123.8,16.739 124.206,17.348 124.866,17.348 124.511,28.448 138.151,46.304 138.836,46.304 139.548,46.304 137.465,46.33 138.252,46.965 138.938,46.965 139.649,46.965 139.954,47.65 140.691,47.65 148.082,50.8 145.466,56.21 129.743,56.413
